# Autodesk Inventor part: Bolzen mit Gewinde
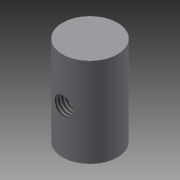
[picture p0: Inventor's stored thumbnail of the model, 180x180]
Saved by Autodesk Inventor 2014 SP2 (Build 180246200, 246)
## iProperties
Created: 2015-04
Part Number: Bolzen mit Gewinde
Material: Generisch
Document SubType Name: Modeling
Designer: e_krauts
Density: 1 g/cm^3
Appearance: Vorgabe
Author: e_krauts
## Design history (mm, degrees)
sketch "Skizze1"
  geometry: C1 r 10 at (0, 0); 1 further point
  constraints: 1 centre point, 1 coincident
  dimensions: "d0" = 20 diameter of C1
extrude "Extrusion1" new body sketch "Skizze1" distance "d1" = 32.5; taper "d2" = 0 deg
workplane "Arbeitsebene1"
sketch "Skizze2"
  geometry: L1 (-10, 0)-(10, 0) reference; 2 further points
  dimensions: "d3" = 16.25 distance from line of L1 point (0, -16.25)
hole "Bohrung1" sketch "Skizze2" at (0, -16.25) diameter "d4" = 6.647; stored, may be unused: countersink angle "d8" = 90 deg, drill point angle "d10" = 118 deg; dims "d5" = 6, "d6" = 4, "d7" = 2, "d9" = 8
node "Volumenkörper1"
